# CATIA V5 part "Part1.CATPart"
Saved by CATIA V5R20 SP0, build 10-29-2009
Part number: Part1
Bounding box of the stored display mesh (mm): x 0 to 0, y -20 to 20, z 0 to 20
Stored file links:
  C:\Documents and Settings\Media\Escritorio\GATO_ALAMBRICO\Part1.CATPart
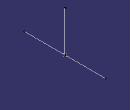
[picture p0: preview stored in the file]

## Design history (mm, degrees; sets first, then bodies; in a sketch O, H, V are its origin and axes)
AxisSystem1: origin (0, 0, 0), X (1, 0, 0), Y (0, 1, 0), Z (0, 0, 1)
Set1
  Point1: (0, 0, 0), in AxisSystem1
  Line1: type PtDir, RefPoint Point1, Direction zx-plane, Start -20, End 20
  Line2: type PtDir, RefPoint Point1, Direction xy-plane, Start 0, End 20
Body1 (main body)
